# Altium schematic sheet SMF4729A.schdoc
size 127 x 101 mm
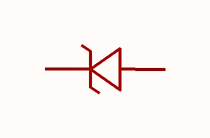
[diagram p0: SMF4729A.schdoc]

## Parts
D?  smf4729a  [SOD-123FL_L2.8-W1.8-LS3.6-RD]  (value not drawn)

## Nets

Not connected (* = marked no-connect by the designer): D? 1(K) 2(A)

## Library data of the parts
D? = smf4729a: 二极管配置:1个独立式;稳压值(标称值):3.6V;稳压值(范围值):3.42V~3.78V;耗散功率(Pd):1W;; Manufacturer: CJ(江苏长电/长晶); AddInBom: yes; ModelId: 9a6bf0a398604d2998ad78800a7c8ef9; ModelTransform: 141.732,70.866,0,0,0,0,0,0,0; Diode Configuration: 1个独立式; Zener Voltage(Nom): 3.6V; Reverse Leakage Current (Ir): 100uA@1V; Pd - Power Dissipation: 1W; Impedance(Zzt): 10Ω; Impedance(Zzk): 400Ω; Operating Junction Temperature Range: -55℃~+150℃; Tolerance: ±5%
